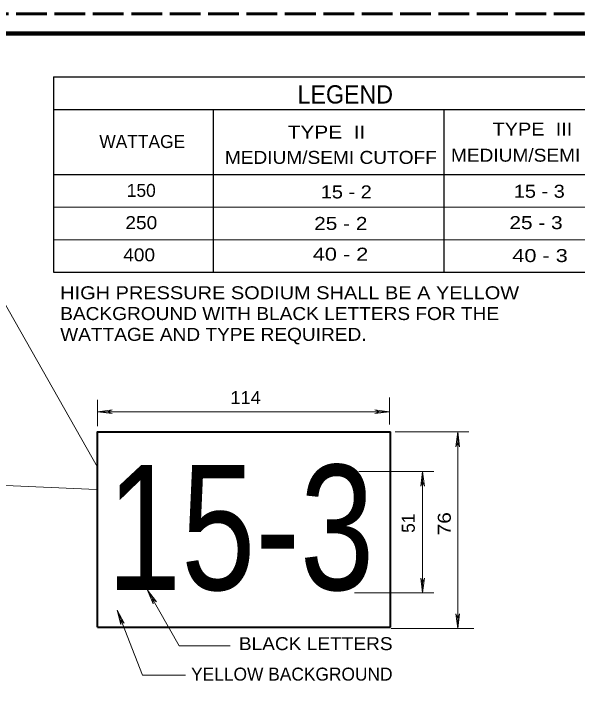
# Model space of a CAD drawing. Extents: x 312583 to 312854, y 144418 to 144597.
# Drawn here: x 312741.83 to 312774.81, y 144545.23 to 144586.22 of the extents above; entities that cross this region are included whole.
import ezdxf
from ezdxf.enums import TextEntityAlignment as Align

# ---------------------------------------------------------------- set-up
doc = ezdxf.new("R2010")
doc.units = 0
doc.header["$LTSCALE"] = 0.3
doc.linetypes.add('LONG_DASHED', pattern=[7.5, 6, -1.5])
doc.layers.add('1', color=7, linetype='Continuous', lineweight=35)
doc.layers.add('2', color=7, linetype='Continuous')

msp = doc.modelspace()

# ---------------------------------------------------------------- linework, layer by layer
at = {"layer": '1', "linetype": 'LONG_DASHED', "lineweight": 60}
msp.add_line((312851.75, 144586.2246), (312583.526, 144586.2246), dxfattribs=at)
at = {"layer": '1', "lineweight": 25}
for p, q in [((312744.1354, 144582.5396), (312744.1354, 144571.1021)), ((312744.1354, 144582.5396), (312779.9628, 144582.5396)), ((312744.1354, 144580.6333), (312779.9628, 144580.6333)), ((312753.4938, 144580.6181), (312753.4938, 144571.1021)), ((312767.0104, 144580.5952), (312767.0104, 144571.1021)), ((312744.1354, 144576.8209), (312779.9628, 144576.8209)), ((312744.1354, 144571.1021), (312779.9628, 144571.1021))]:
    msp.add_line(p, q, dxfattribs=at)
at = {"layer": '1', "lineweight": 40}
for p, q in [((312755.5729, 144582.5396), (312755.5729, 144582.5243)), ((312763.8828, 144550.3086), (312763.8828, 144561.746)), ((312746.7189, 144550.3086), (312763.8828, 144550.3086))]:
    msp.add_line(p, q, dxfattribs=at)
at = {"layer": '1', "lineweight": 13}
for p, q in [((312736.0291, 144578.5439), (312746.7112, 144559.6797)), ((312744.1354, 144574.9146), (312779.9628, 144574.9146)), ((312744.1354, 144573.0083), (312779.9628, 144573.0083)), ((312746.7189, 144562.0816), (312746.7189, 144563.637)), ((312763.8218, 144562.1883), (312763.8218, 144563.7667)), ((312746.7189, 144562.9279), (312747.5805, 144563.0347)), ((312747.5805, 144563.0347), (312747.306, 144562.9279)), ((312762.9601, 144563.0347), (312763.2346, 144562.9279)), ((312763.8218, 144562.9279), (312762.9601, 144563.0347)), ((312746.7189, 144562.9279), (312763.8218, 144562.9279)), ((312746.7189, 144562.9279), (312747.5805, 144562.8212)), ((312747.5805, 144562.8212), (312747.306, 144562.9279)), ((312762.9601, 144562.8212), (312763.2346, 144562.9279)), ((312763.8218, 144562.9279), (312762.9601, 144562.8212)), ((312764.1572, 144561.746), (312768.4654, 144561.746)), ((312767.8249, 144561.746), (312767.7181, 144560.8844)), ((312767.8249, 144550.2323), (312767.8249, 144561.746)), ((312767.8249, 144561.746), (312767.9316, 144560.8844)), ((312767.7181, 144560.8844), (312767.8249, 144561.1589)), ((312767.9316, 144560.8844), (312767.8249, 144561.1589)), ((312762.0375, 144559.428), (312766.4142, 144559.428)), ((312765.7593, 144559.428), (312765.6526, 144558.5664)), ((312765.7593, 144552.3216), (312765.7593, 144559.428)), ((312765.7593, 144559.428), (312765.8661, 144558.5664)), ((312726.8944, 144559.2374), (312746.6655, 144558.3758)), ((312765.6526, 144558.5664), (312765.7593, 144558.8409)), ((312765.8661, 144558.5664), (312765.7593, 144558.8409)), ((312765.6526, 144553.1832), (312765.7593, 144552.9087)), ((312765.7593, 144552.3216), (312765.6526, 144553.1832)), ((312765.8661, 144553.1832), (312765.7593, 144552.9087)), ((312765.7593, 144552.3216), (312765.8661, 144553.1832)), ((312751.4998, 144549.2258), (312749.6469, 144552.4893)), ((312749.6469, 144552.4893), (312749.9824, 144551.6887)), ((312749.6469, 144552.4893), (312750.1654, 144551.7954)), ((312749.9824, 144551.6887), (312749.9366, 144551.9784)), ((312750.1654, 144551.7954), (312749.9366, 144551.9784)), ((312761.7706, 144552.3216), (312766.4142, 144552.3216)), ((312749.3495, 144547.5102), (312747.8626, 144551.315)), ((312747.8626, 144551.315), (312748.0761, 144550.4763)), ((312747.8626, 144551.315), (312748.2744, 144550.5526)), ((312748.0761, 144550.4763), (312748.0761, 144550.766)), ((312748.2744, 144550.5526), (312748.0761, 144550.766)), ((312767.7181, 144551.0939), (312767.8249, 144550.8194)), ((312767.8249, 144550.2323), (312767.7181, 144551.0939)), ((312767.9316, 144551.0939), (312767.8249, 144550.8194)), ((312767.8249, 144550.2323), (312767.9316, 144551.0939)), ((312763.9209, 144550.2323), (312768.7704, 144550.2323)), ((312754.4964, 144549.2258), (312751.4998, 144549.2258)), ((312751.8734, 144547.5102), (312749.3495, 144547.5102))]:
    msp.add_line(p, q, dxfattribs=at)
at = {"layer": '1', "lineweight": 158}
msp.add_lwpolyline([(312849, 144423.0846), (312849, 144585.0846), (312616.5, 144585.0846), (312616.5, 144423.0846)], close=True, dxfattribs=at)
at = {"layer": '1', "lineweight": 40}
msp.add_lwpolyline([(312746.7189, 144550.3086), (312746.7189, 144561.746), (312763.8828, 144561.746)], dxfattribs=at)

# ---------------------------------------------------------------- texts
at = {"layer": '1'}
for s, height, width, p in [('LEGEND', 1.07, 0.95, (312761.2356, 144580.9807)), ('15-3', 7.32, 0.8, (312755.0949, 144552.4969))]:
    msp.add_text(s, height=height, dxfattribs=dict(at, width=width)).set_placement(p, align=Align.CENTER)
for s, width, p in [('TYPE  III', 1.15, (312769.8591, 144579.1039)), ('TYPE  II', 1.2, (312757.8627, 144578.9286)), ('MEDIUM/SEMI CUTOFF', 1.1, (312754.1793, 144577.4466)), ('MEDIUM/SEMI CUTOFF', 1.1, (312767.4269, 144577.5748)), ('15 - 2', 1.15, (312759.7983, 144575.4245)), ('15 - 3', 1.15, (312771.1062, 144575.4626)), ('250', 1.1, (312748.3507, 144573.6251)), ('25 - 2', 1.2, (312759.4119, 144573.5793)), ('25 - 3', 1.2, (312770.8494, 144573.625)), ('400', 1.1, (312748.2248, 144571.7404)), ('40 - 2', 1.25, (312759.3314, 144571.7797)), ('40 - 3', 1.25, (312771.0206, 144571.6959)), ('114 ', 1.05, (312754.5036, 144563.3801)), ('BLACK LETTERS', 1.1, (312754.9996, 144548.969))]:
    msp.add_text(s, height=0.76, dxfattribs=dict(at, width=width)).set_placement(p)
for s, p in [('WATTAGE', (312746.8265, 144578.3755)), ('150', (312748.4347, 144575.5133)), ('YELLOW BACKGROUND', (312752.2012, 144547.1848))]:
    msp.add_text(s, height=0.76, dxfattribs=at).set_placement(p)
msp.add_text('51 ', height=0.76, rotation=90, dxfattribs=at).set_placement((312765.3058, 144555.8375))
at = {"layer": '1', "width": 1.2}
msp.add_text('76 ', height=0.76, rotation=90, dxfattribs=at).set_placement((312767.4164, 144555.693))
at = {"layer": '2'}
for s, width, p in [('HIGH PRESSURE SODIUM SHALL BE A YELLOW', 1.15, (312744.5319, 144569.5186)), ('BACKGROUND WITH BLACK LETTERS FOR THE', 1.1, (312744.5319, 144568.3011)), ('WATTAGE AND TYPE REQUIRED.', 1.1, (312744.5319, 144567.0836))]:
    msp.add_text(s, height=0.76, dxfattribs=dict(at, width=width)).set_placement(p)

doc.saveas('drawing.dxf')
